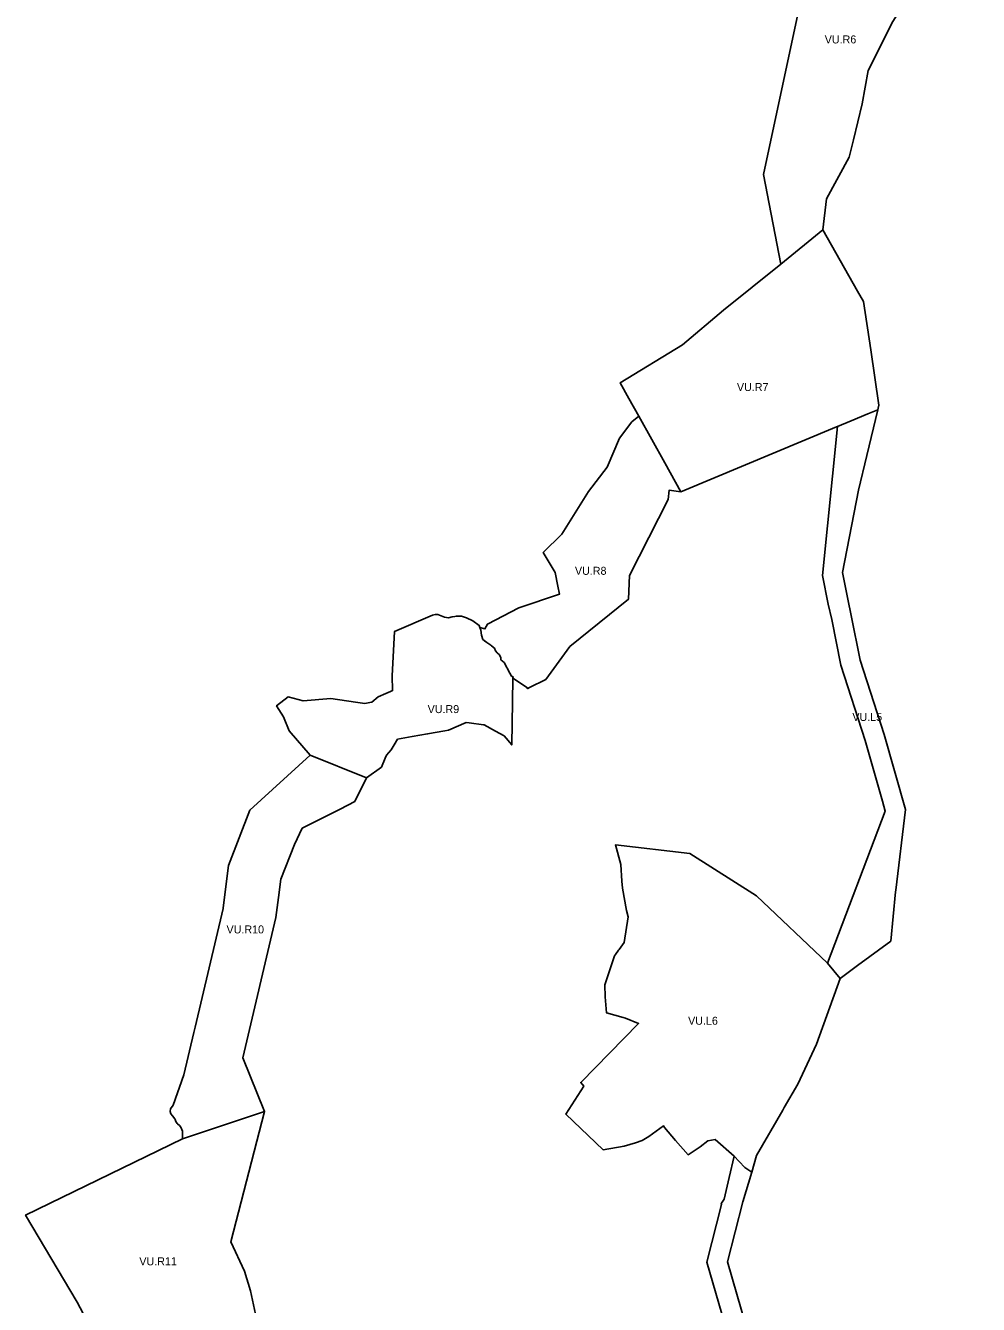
# Model space of a CAD drawing. Extents: x -439083 to -433688, y -1130252 to -1121189.
# Drawn here: x -435713 to -434285, y -1125151 to -1123234 of the extents above; entities that cross this region are included whole.
import ezdxf

# ---------------------------------------------------------------- set-up
doc = ezdxf.new("R2010")
doc.units = 0
doc.layers.add('Vrstva 28', color=7, linetype='Continuous')
doc.layers.add('Vrstva 31', color=7, linetype='Continuous')

msp = doc.modelspace()

# ---------------------------------------------------------------- linework, layer by layer
at = {"layer": 'Vrstva 28'}
for p, q in [((-434580.6, -1123591.5), (-434518, -1123539.7)), ((-434518, -1123539.7), (-434580.6, -1123591.5)), ((-434580.6, -1123591.6), (-434583, -1123593.5)), ((-434580.6, -1123591.5), (-434580.6, -1123591.6)), ((-434808.4, -1123792.6), (-434793.5, -1123819.2)), ((-434475.1, -1123826.3), (-434450.3, -1123816)), ((-434450.3, -1123816), (-434475.1, -1123826.3)), ((-434450.3, -1123816), (-434435.2, -1123809.7)), ((-434435.2, -1123809.7), (-434450.3, -1123816)), ((-434475.1, -1123826.3), (-434495.6, -1123834.8)), ((-435030.2, -1124139.9), (-435031.7, -1124136)), ((-435030.2, -1124139.9), (-435029.4, -1124147.6)), ((-435029.4, -1124147.6), (-435030.2, -1124139.9)), ((-435027.6, -1124153.9), (-435029.4, -1124147.6)), ((-435015.3, -1124162.7), (-435021.5, -1124158.7)), ((-435015.3, -1124162.7), (-435014.5, -1124163.4)), ((-435014.5, -1124163.4), (-435015.3, -1124162.7)), ((-435014.5, -1124163.4), (-435010.1, -1124166.9)), ((-435010.1, -1124166.9), (-435014.5, -1124163.4)), ((-435005.9, -1124174.1), (-435002.4, -1124177.2)), ((-435002.4, -1124177.2), (-435005.9, -1124174.1)), ((-435002.4, -1124177.2), (-435000.6, -1124181.5)), ((-435000.6, -1124181.5), (-435000.3, -1124182.2)), ((-434995.4, -1124188.5), (-435000.3, -1124184.4)), ((-434995.4, -1124188.5), (-434986.8, -1124204.8)), ((-434986.8, -1124204.8), (-434984.6, -1124209)), ((-434984.6, -1124209), (-434983, -1124209.5)), ((-434983, -1124209.5), (-434982, -1124210)), ((-434982, -1124210), (-434982.2, -1124212.3)), ((-435286, -1124327.5), (-435201.7, -1124361.3)), ((-435201.7, -1124361.3), (-435286, -1124327.5)), ((-435387.2, -1124781.1), (-435337.5, -1124570.8)), ((-434511, -1124639.1), (-434491.8, -1124662.2)), ((-434491.8, -1124662.2), (-434511, -1124639.1)), ((-434491.8, -1124662.2), (-434465.6, -1124642.8)), ((-434650.5, -1124928.8), (-434643.1, -1124936.6)), ((-434643.1, -1124936.6), (-434650.5, -1124928.8)), ((-434643.1, -1124936.6), (-434634.6, -1124945.5)), ((-434634.6, -1124945.5), (-434643.1, -1124936.6)), ((-434634.6, -1124945.5), (-434624.4, -1124952.6)), ((-434624.4, -1124952.6), (-434634.6, -1124945.5))]:
    msp.add_line(p, q, dxfattribs=at)
for points in [[(-434518, -1123539.7), (-434512.4, -1123493.4), (-434478.2, -1123431.2), (-434471.9, -1123405.2), (-434458.9, -1123351.3), (-434449.8, -1123301), (-434412.9, -1123227.4), (-434389.6, -1123189.4), (-434377.2, -1123169.1), (-434354, -1123131.2), (-434332, -1123096.3), (-434320.8, -1123078.5), (-434314.4, -1123051.7), (-434304.3, -1123038.5), (-434301.1, -1123031.3), (-434299.7, -1123028.1), (-434295.7, -1123018.7), (-434284.6, -1123005.4), (-434324.5, -1123013.7)], [(-434447.2, -1123063.3), (-434478.5, -1123094.9), (-434507.9, -1123124.6), (-434543.2, -1123160.2), (-434606.8, -1123457.2), (-434580.6, -1123591.5)], [(-434435.2, -1123809.7), (-434434.6, -1123807.1), (-434433.6, -1123802.9), (-434445.9, -1123719.6), (-434456.8, -1123647.3), (-434465.7, -1123631.7), (-434518, -1123539.7)], [(-434583, -1123593.5), (-434580.6, -1123591.5), (-434666.9, -1123660.3), (-434728.1, -1123712.1), (-434821.5, -1123769.2), (-434808.4, -1123792.6)], [(-434793.5, -1123819.2), (-434804, -1123827.8), (-434822.5, -1123852.2), (-434841, -1123895.9), (-434868.8, -1123932.3), (-434909, -1123996.3), (-434936.9, -1124023.5), (-434918.7, -1124053.4), (-434915.1, -1124074.2), (-434912.7, -1124086.2), (-434973.2, -1124106.6), (-435020.3, -1124131.1), (-435024.3, -1124138.1), (-435031.7, -1124136), (-435030.2, -1124139.9)], [(-434793.5, -1123819.2), (-434793.3, -1123819.1), (-434754.4, -1123889.2), (-434730.8, -1123932.7)], [(-434730.8, -1123932.7), (-434754.4, -1123889.2), (-434793.5, -1123819.2)], [(-434465.6, -1124642.8), (-434416.1, -1124606.3), (-434408.7, -1124532.3), (-434408.3, -1124529.8), (-434393.8, -1124408.9), (-434425.6, -1124296.7), (-434461.6, -1124184.9), (-434475.1, -1124118.3), (-434480.2, -1124093.6), (-434488.3, -1124053.7), (-434464.2, -1123930.2), (-434451.7, -1123878.3), (-434435.2, -1123809.7)], [(-434730.8, -1123932.7), (-434497.3, -1123835.5), (-434495.6, -1123834.8), (-434475.1, -1123826.3)], [(-434495.6, -1123834.8), (-434518.1, -1124058), (-434509.8, -1124101.1), (-434504.5, -1124124.3), (-434490.6, -1124192.5), (-434454.3, -1124305.4), (-434428.5, -1124396.4), (-434424.3, -1124411.3), (-434511, -1124639.1)], [(-434982.2, -1124212.3), (-434972.3, -1124218.8), (-434961.4, -1124225.8), (-434960.3, -1124227.6), (-434959.7, -1124227.3), (-434957.5, -1124226.2), (-434933.1, -1124214.3), (-434897, -1124164.8), (-434809.2, -1124093.7), (-434807.3, -1124058.1), (-434749.6, -1123944.2), (-434748, -1123930.1), (-434730.8, -1123932.7)], [(-435031.7, -1124136), (-435032.9, -1124132.9), (-435042.4, -1124126.2), (-435051.8, -1124121.6), (-435059.4, -1124119.3), (-435060.9, -1124119.3), (-435067.1, -1124119.3), (-435069.2, -1124119.6), (-435073.4, -1124120.2), (-435078.6, -1124121.5), (-435085, -1124120.7), (-435089.6, -1124118.6), (-435094.7, -1124116.8), (-435098.9, -1124116.8), (-435103, -1124117.7), (-435159.8, -1124142.3), (-435163.5, -1124208.7), (-435162.6, -1124230.6), (-435165.6, -1124231.9), (-435172.9, -1124235.2), (-435184.4, -1124240.2), (-435193.6, -1124247.9), (-435194.4, -1124248.1), (-435204.4, -1124249.9), (-435218.1, -1124247.9), (-435255.4, -1124242.4), (-435296.4, -1124245.8), (-435318.9, -1124240.1), (-435336.5, -1124253.5), (-435326.2, -1124270), (-435317.7, -1124290.9), (-435317.7, -1124291.1), (-435286, -1124327.5)], [(-435029.4, -1124147.6), (-435027.6, -1124153.9), (-435021.5, -1124158.7), (-435015.3, -1124162.7)], [(-435021.5, -1124158.7), (-435022.9, -1124157.8), (-435027.6, -1124153.9)], [(-435010.1, -1124166.9), (-435008.4, -1124171.3), (-435005.9, -1124174.1)], [(-435005.9, -1124174.1), (-435008.4, -1124171.3), (-435010.1, -1124166.9)], [(-435000.3, -1124184.4), (-435000.3, -1124182.2), (-435000.6, -1124181.5), (-435002.4, -1124177.2)], [(-435000.3, -1124182.2), (-435000.3, -1124184.4), (-434995.4, -1124188.5)], [(-434984.6, -1124209), (-434986.8, -1124204.8), (-434995.4, -1124188.5)], [(-435201.7, -1124361.3), (-435179.4, -1124345.3), (-435173.9, -1124332.2), (-435171.9, -1124327.6), (-435168.5, -1124323.6), (-435164.9, -1124319.5), (-435160.3, -1124312.1), (-435155.1, -1124303.6), (-435133.1, -1124299.7), (-435110.1, -1124295.7), (-435084.4, -1124291.1), (-435078.6, -1124290.1), (-435052.5, -1124278.4), (-435047.9, -1124279), (-435026.2, -1124281.9), (-435025.5, -1124282), (-435008.4, -1124291.3), (-434995.6, -1124298.7), (-434984.1, -1124312), (-434982.9, -1124247.3), (-434982.2, -1124212.3)], [(-434982.2, -1124212.3), (-434983, -1124209.5), (-434984.6, -1124209)], [(-435286, -1124327.5), (-435376.7, -1124410), (-435408.4, -1124493), (-435416.4, -1124556.6), (-435416.6, -1124557.3), (-435458.7, -1124735.5), (-435460.4, -1124743), (-435475.5, -1124806.7), (-435491.3, -1124852.1), (-435495.5, -1124857.5), (-435496, -1124861.8), (-435495.1, -1124865), (-435492.5, -1124868.4), (-435488.8, -1124872.7), (-435488.5, -1124873.7), (-435487.6, -1124876.7), (-435485.6, -1124879.6), (-435485.2, -1124880.1), (-435482.1, -1124882.6), (-435480.1, -1124885), (-435477.4, -1124891.1), (-435477.4, -1124902.8), (-435354.5, -1124861.6), (-435387.2, -1124781.1)], [(-435337.5, -1124570.8), (-435333.8, -1124540.7), (-435330.3, -1124513.2), (-435309.5, -1124461.4), (-435298, -1124437.1), (-435241, -1124408.4), (-435219.3, -1124396.7), (-435201.7, -1124361.3)], [(-434511, -1124639.1), (-434617, -1124538.6), (-434717, -1124475), (-434828.7, -1124462), (-434820.7, -1124491.5), (-434818.8, -1124516.3), (-434818, -1124527), (-434812.2, -1124560.4), (-434809.6, -1124570), (-434815.6, -1124608.4), (-434823, -1124618.6), (-434823.8, -1124619.6), (-434828.7, -1124626.3), (-434830, -1124628.1), (-434838.7, -1124654), (-434844.7, -1124671.9), (-434843.8, -1124689.7), (-434841.8, -1124713.9), (-434817.2, -1124720.6), (-434813.3, -1124721.6)], [(-434624.4, -1124952.6), (-434617, -1124927.6), (-434577.7, -1124859.5), (-434575.5, -1124855.6), (-434555.3, -1124820.5), (-434527.1, -1124760.6), (-434491.8, -1124662.2)], [(-434813.3, -1124721.6), (-434794, -1124730), (-434880.5, -1124818.2), (-434876.1, -1124823.7), (-434903, -1124865.8), (-434847.1, -1124919), (-434815.7, -1124913.6), (-434798.5, -1124908.7), (-434788.4, -1124905.3), (-434778.5, -1124899.2), (-434756.5, -1124883.3), (-434755.2, -1124885.6), (-434738.6, -1124905.1), (-434719.4, -1124926.6), (-434701.5, -1124914.4), (-434690.1, -1124905.6), (-434679, -1124903.6), (-434650.5, -1124928.8)], [(-435468.6, -1125221.4), (-435359.9, -1125203.1), (-435368.1, -1125165.7), (-435375.8, -1125130.7), (-435384.8, -1125101), (-435405.2, -1125057), (-435354.5, -1124861.6), (-435477.4, -1124902.8), (-435712.7, -1125017), (-435635.3, -1125147.3), (-435613.5, -1125189), (-435595.6, -1125199.5), (-435546.1, -1125209.4), (-435477.7, -1125222.9)], [(-434650.5, -1124928.8), (-434658.2, -1124960.8), (-434665.8, -1124992.9), (-434668.7, -1124997.5), (-434670.1, -1124999.6), (-434669.7, -1125001.3), (-434691.7, -1125087.6), (-434660.3, -1125195.8)], [(-434632.5, -1125184.1), (-434660.6, -1125087.1), (-434637.7, -1124997.1), (-434624.4, -1124952.6)]]:
    msp.add_lwpolyline(points, dxfattribs=at)

# ---------------------------------------------------------------- texts
at = {"layer": 'Vrstva 31'}
for s, p in [('VU.R6', (-434514.9, -1123260.5)), ('VU.R7', (-434646.5, -1123781.6)), ('VU.R8', (-434889.3, -1124057.1)), ('VU.R9', (-435110.1, -1124264.4)), ('VU.L5', (-434473.5, -1124276.2)), ('VU.R10', (-435411.5, -1124594.7)), ('VU.L6', (-434719.7, -1124731.6)), ('VU.R11', (-435542.2, -1125092.3))]:
    msp.add_text(s, height=12, dxfattribs=at).set_placement(p)

doc.saveas('drawing.dxf')
